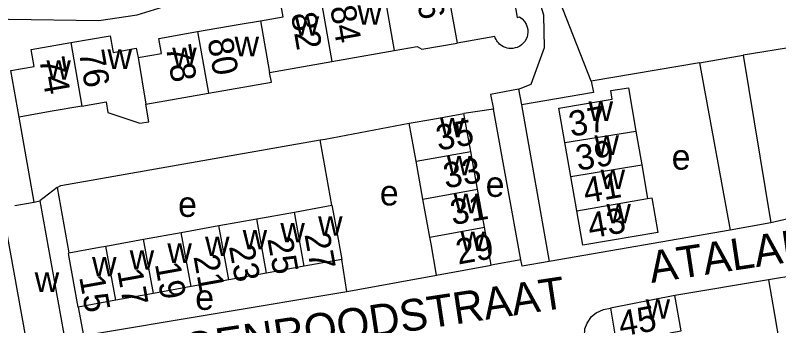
# Model space of a CAD drawing. Extents: x 162883 to 165538, y 383986 to 385172.
# Drawn here: x 164517.2 to 164637.8, y 384508.3 to 384557.3 of the extents above; entities that cross this region are included whole.
import ezdxf

# ---------------------------------------------------------------- set-up
doc = ezdxf.new("R2010")
doc.units = 0
for name, color, linetype in [('BLT_Basislijn', 7, 'Continuous'), ('BLT_Bebouwing', 7, 'Continuous'), ('BLT_Centroide', 7, 'Continuous'), ('BLT_Huisnummer', 7, 'Continuous'), ('BLT_Huisnummer_ tussenligend', 7, 'Continuous'), ('BLT_Onderverdeling_panden', 7, 'Continuous'), ('BLT_Straatnaam', 7, 'Continuous')]:
    doc.layers.add(name, color=color, linetype=linetype)

msp = doc.modelspace()

# ---------------------------------------------------------------- linework, layer by layer
at = {"layer": 'BLT_Basislijn'}
for p, q in [((164655.25, 384554.82), (164632.12, 384550.99)), ((164625.22, 384549.8), (164632.12, 384550.99)), ((164632.12, 384550.99), (164636.49, 384524.5)), ((164625.22, 384549.8), (164608.15, 384546.89)), ((164625.22, 384549.8), (164630.09, 384523.38)), ((164596.69, 384545.66), (164597.13, 384543.14)), ((164592.7, 384542.48), (164588.05, 384541.8)), ((164597.03, 384518.69), (164592.7, 384542.48)), ((164597.13, 384543.14), (164601.51, 384518.42)), ((164520.18, 384527.81), (164517.81, 384541.23)), ((164567.21, 384527.3), (164565.35, 384537.61)), ((164523.82, 384530.1), (164521.06, 384527.97)), ((164523.82, 384530.1), (164525.67, 384519.8)), ((164648.27, 384527.21), (164636.49, 384524.5)), ((164636.49, 384524.5), (164630.09, 384523.38)), ((164630.09, 384523.38), (164601.51, 384518.42)), ((164569.57, 384513.66), (164568.76, 384518.74)), ((164597.03, 384518.69), (164592.37, 384517.83)), ((164643.1, 384516.71), (164636.16, 384515.5)), ((164636.16, 384515.5), (164621.37, 384513.05)), ((164636.16, 384515.5), (164637.1, 384510.03)), ((164637.1, 384510.03), (164638.84, 384500))]:
    msp.add_line(p, q, dxfattribs=at)
for points in [[(164596.69, 384545.66), (164598.65, 384546.43), (164600.76, 384552.19), (164600.65, 384557.32), (164600.04, 384559.39), (164596.6, 384568.19), (164594.84, 384571.97), (164594.6, 384572.45), (164594.19, 384572.88), (164593.74, 384573.11), (164593.29, 384573.18), (164587.03, 384572.69), (164569.42, 384569.95)], [(164515.11, 384556.74), (164516.15, 384556.71), (164530.41, 384556.48), (164536.46, 384557.35), (164544, 384559.73), (164552.89, 384564.9), (164556.58, 384566.59), (164561.28, 384567.83), (164564.73, 384567.77), (164568.27, 384566.96), (164569.42, 384569.95)], [(164608.15, 384546.89), (164601.4, 384564.14)], [(164608.15, 384546.89), (164608.49, 384545.09), (164597.13, 384543.14)], [(164596.69, 384545.66), (164592.24, 384544.8), (164592.7, 384542.48)], [(164565.35, 384537.61), (164566.16, 384537.75), (164579.41, 384540.24)], [(164523.82, 384530.1), (164524.38, 384530.42), (164565.35, 384537.61)], [(164601.51, 384518.42), (164597.22, 384517.67), (164597.03, 384518.69)], [(164569.57, 384513.66), (164570.44, 384513.81), (164583.74, 384516.27)], [(164527.12, 384511.22), (164527.97, 384506.72), (164569.57, 384513.66)], [(164608.29, 384500), (164607.09, 384506.6), (164607.15, 384507.76), (164607.52, 384508.66), (164608.17, 384509.73), (164608.95, 384510.3), (164610.09, 384510.83), (164611.18, 384511.02)]]:
    msp.add_lwpolyline(points, dxfattribs=at)
at = {"layer": 'BLT_Bebouwing'}
for p, q in [((164557.32, 384548.29), (164567.17, 384550.01)), ((164517.81, 384541.23), (164516.52, 384548.57)), ((164589.13, 384535.81), (164588.05, 384541.8)), ((164580.49, 384534.25), (164579.41, 384540.24)), ((164615.2, 384539.02), (164616.13, 384533.69)), ((164604.93, 384531.82), (164603.98, 384537.22)), ((164590.21, 384529.82), (164589.13, 384535.81)), ((164581.57, 384528.26), (164580.49, 384534.25)), ((164605.88, 384526.41), (164604.93, 384531.82)), ((164591.29, 384523.83), (164590.21, 384529.82)), ((164517.13, 384527.26), (164520.18, 384527.81)), ((164520.18, 384527.81), (164521.06, 384527.97)), ((164582.65, 384522.27), (164581.57, 384528.26)), ((164561.27, 384526.23), (164567.21, 384527.3)), ((164549.37, 384524.08), (164555.32, 384525.15)), ((164555.32, 384525.15), (164561.27, 384526.23)), ((164543.42, 384523), (164549.37, 384524.08)), ((164537.47, 384521.93), (164543.42, 384523)), ((164592.37, 384517.83), (164591.29, 384523.83)), ((164531.52, 384520.86), (164537.47, 384521.93)), ((164525.59, 384519.68), (164525.67, 384519.8)), ((164527.12, 384511.22), (164525.59, 384519.68)), ((164568.76, 384518.74), (164562.81, 384517.66)), ((164562.81, 384517.66), (164556.86, 384516.59)), ((164583.74, 384516.27), (164592.37, 384517.83)), ((164550.92, 384515.52), (164544.97, 384514.44)), ((164556.86, 384516.59), (164550.92, 384515.52)), ((164544.97, 384514.44), (164539.02, 384513.37)), ((164539.02, 384513.37), (164533.07, 384512.3)), ((164533.07, 384512.3), (164527.12, 384511.22)), ((164621.37, 384513.05), (164611.18, 384511.02)), ((164611.18, 384511.02), (164612.1, 384505.69))]:
    msp.add_line(p, q, dxfattribs=at)
for points in [[(164584.88, 384564.75), (164591.1, 384565.84), (164591.54, 384563.29), (164595.24, 384563.94), (164596.46, 384556.98)], [(164555.92, 384556.45), (164559.52, 384557.06), (164559.21, 384558.82), (164565.44, 384559.91)], [(164596.46, 384556.98), (164596.81, 384557.04), (164597.23, 384556.74), (164597.62, 384556.33), (164597.87, 384555.9), (164598.04, 384555.45), (164598.13, 384555.04), (164598.15, 384554.64), (164598.1, 384554.23), (164598.02, 384553.91), (164597.86, 384553.54), (164597.64, 384553.16), (164597.4, 384552.88), (164597.16, 384552.64), (164596.87, 384552.44), (164596.48, 384552.24), (164596.14, 384552.14), (164595.79, 384552.07), (164595.43, 384552.04), (164595.16, 384552.06), (164594.85, 384552.12), (164594.59, 384552.2), (164594.3, 384552.32), (164594.04, 384552.47), (164593.85, 384552.6), (164593.66, 384552.75), (164593.51, 384552.93), (164593.34, 384553.12), (164593.24, 384553.25), (164593.12, 384553.46), (164593, 384553.72), (164592.92, 384553.95), (164586.96, 384552.91)], [(164546, 384554.73), (164552.4, 384555.84), (164555.92, 384556.45)], [(164525.97, 384552.99), (164532.21, 384554.08), (164532.67, 384551.44), (164536.28, 384552.1), (164536.6, 384550.63)], [(164536.6, 384550.63), (164540.28, 384551.27), (164539.87, 384553.66), (164546, 384554.73)], [(164516.52, 384548.57), (164520.2, 384549.21), (164519.73, 384551.9), (164525.97, 384552.99)], [(164577.03, 384551.73), (164580.68, 384552.37), (164581.38, 384551.93), (164586.96, 384552.91)], [(164567.17, 384550.01), (164577.03, 384551.73)], [(164547.7, 384544.99), (164557.68, 384546.73), (164557.32, 384548.29)], [(164603.98, 384537.22), (164603.04, 384542.63), (164611.48, 384544.03), (164611.26, 384545.4), (164614.02, 384545.85), (164615.2, 384539.02)], [(164537.8, 384543.26), (164547.7, 384544.99)], [(164527.72, 384542.96), (164531.55, 384543.62), (164531.84, 384541.96), (164536.87, 384540.24), (164538.29, 384540.49), (164537.8, 384543.26)], [(164527.72, 384542.96), (164522.73, 384542.09), (164517.81, 384541.23)], [(164579.41, 384540.24), (164583.13, 384540.91), (164588.05, 384541.8)], [(164616.13, 384533.69), (164617.05, 384528.35)], [(164521.06, 384527.97), (164525.33, 384504.32), (164519.46, 384503.26), (164515.19, 384526.91)], [(164617.05, 384528.35), (164617.74, 384528.47), (164618.69, 384523.01), (164606.83, 384521), (164605.88, 384526.41)], [(164567.21, 384527.3), (164567.87, 384523.66), (164568.76, 384518.74)], [(164583.74, 384516.27), (164582.85, 384521.2), (164582.65, 384522.27)], [(164525.67, 384519.8), (164530.49, 384520.67), (164531.52, 384520.86)], [(164620.55, 384507.16), (164622.34, 384507.47), (164621.37, 384513.05)]]:
    msp.add_lwpolyline(points, dxfattribs=at)
at = {"layer": 'BLT_Onderverdeling_panden'}
for p, q in [((164584.88, 384564.75), (164586.96, 384552.91)), ((164575.5, 384560.48), (164577.03, 384551.73)), ((164565.44, 384559.91), (164567.17, 384550.01)), ((164555.92, 384556.45), (164557.32, 384548.29)), ((164546, 384554.73), (164547.7, 384544.99)), ((164525.97, 384552.99), (164527.72, 384542.96)), ((164536.6, 384550.63), (164537.8, 384543.26)), ((164603.98, 384537.22), (164615.2, 384539.02)), ((164580.49, 384534.25), (164589.13, 384535.81)), ((164604.93, 384531.82), (164616.13, 384533.69)), ((164581.57, 384528.26), (164590.21, 384529.82)), ((164605.88, 384526.41), (164617.05, 384528.35)), ((164556.86, 384516.59), (164555.32, 384525.15)), ((164562.81, 384517.66), (164561.27, 384526.23)), ((164550.92, 384515.52), (164549.37, 384524.08)), ((164544.97, 384514.44), (164543.42, 384523)), ((164582.65, 384522.27), (164591.29, 384523.83)), ((164539.02, 384513.37), (164537.47, 384521.93)), ((164533.07, 384512.3), (164531.52, 384520.86))]:
    msp.add_line(p, q, dxfattribs=at)

# ---------------------------------------------------------------- texts
at = {"layer": 'BLT_Centroide'}
for s, p in [('w', (164571.23, 384555.81)), ('w', (164561.33, 384554.09)), ('w', (164551.83, 384550.83)), ('w', (164531.77, 384548.83)), ('w', (164541.98, 384549.11)), ('w', (164522.12, 384547.14)), ('w', (164607.73, 384540.62)), ('w', (164584.27, 384538.03)), ('w', (164608.66, 384535.25)), ('e', (164620.85, 384532.92)), ('w', (164585.35, 384532.03)), ('w', (164609.62, 384529.84)), ('e', (164591.48, 384528.62)), ('e', (164574.77, 384527.27)), ('w', (164586.43, 384526.03)), ('e', (164542.91, 384525.46)), ('w', (164610.55, 384524.44)), ('w', (164565.02, 384522.48)), ('w', (164559.06, 384521.42)), ('w', (164553.11, 384520.33)), ('w', (164587.51, 384520.06)), ('w', (164547.17, 384519.27)), ('w', (164541.22, 384518.19)), ('w', (164529.33, 384516.05)), ('w', (164535.27, 384517.11)), ('w', (164520.27, 384513.61)), ('e', (164545.62, 384510.77)), ('w', (164616.73, 384509.38))]:
    msp.add_text(s, height=4, dxfattribs=at).set_placement(p)
at = {"layer": 'BLT_Huisnummer'}
for s, rotation, p in [('82', 279.9079, (164560.71, 384557.47)), ('78', 279.9063, (164540.95, 384552.36)), ('74', 279.8997, (164520.96, 384550.44)), ('37', 9.9419, (164604.97, 384538.1)), ('35', 10.2307, (164584, 384535.91)), ('43', 9.9419, (164607.97, 384522.04)), ('27', 280.2353, (164562.85, 384522.7)), ('29', 10.236, (164587.14, 384517.92)), ('23', 280.2353, (164550.93, 384520.8)), ('19', 280.2353, (164539.24, 384518.03)), ('15', 280.2353, (164527.28, 384515.97)), ('45', 9.8609, (164612.82, 384506.55))]:
    msp.add_text(s, height=4, rotation=rotation, dxfattribs=at).set_placement(p)
at = {"layer": 'BLT_Huisnummer_ tussenligend'}
for s, rotation, p in [('86', 279.9079, (164580.16, 384562.28)), ('84', 279.9079, (164566.9, 384558.55)), ('80', 279.9063, (164547.54, 384553.43)), ('76', 279.8997, (164527.23, 384551.5)), ('39', 9.9419, (164606.05, 384532.72)), ('33', 10.236, (164585.15, 384529.93)), ('41', 9.9419, (164607.26, 384527.59)), ('31', 10.236, (164586.26, 384524.14)), ('25', 280.2353, (164556.99, 384522)), ('21', 280.2353, (164545.33, 384519.2)), ('17', 280.2353, (164533.28, 384516.99))]:
    msp.add_text(s, height=4, rotation=rotation, dxfattribs=at).set_placement(p)
at = {"layer": 'BLT_Straatnaam'}
for s, p in [('ATALANTASTRAAT', (164617.65, 384515.01)), ('MORGENROODSTRAAT', (164528.65, 384499.71))]:
    msp.add_text(s, height=4.9999, rotation=8.5838, dxfattribs=at).set_placement(p)

doc.saveas('drawing.dxf')
